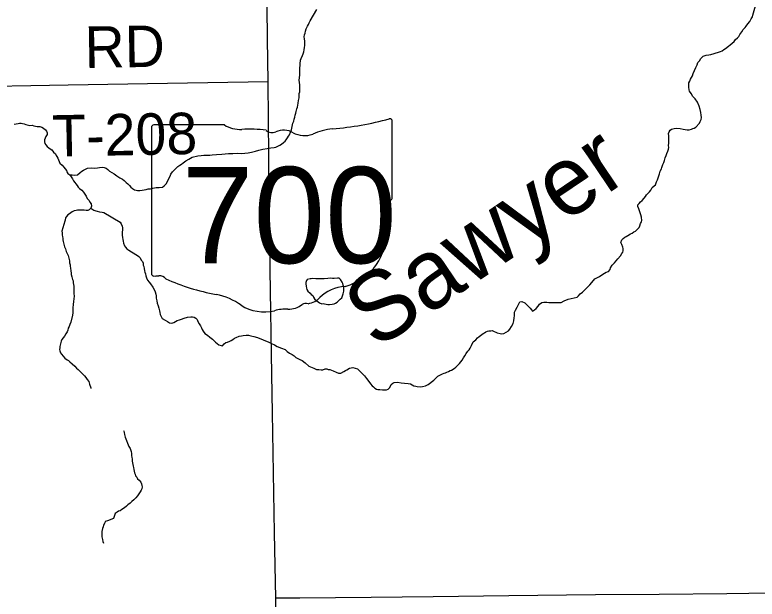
# Model space of a CAD drawing. Extents: x 0 to 34, y 0 to 22.
# Drawn here: x 6.59 to 7.606, y 15.407 to 16.207 of the extents above; entities that cross this region are included whole.
import ezdxf

# ---------------------------------------------------------------- set-up
doc = ezdxf.new("R2010")
doc.units = 0
for name, color, linetype in [('GM_X_Minor_Lake', 7, 'Continuous'), ('GM_X_Minor_River', 7, 'Continuous'), ('GM_X_Minor_River_Text', 7, 'Continuous'), ('GM_X_State_Route', 7, 'Continuous'), ('GM_X_State_Shield', 7, 'Continuous'), ('GM_X_Township_Road', 7, 'Continuous'), ('GM_X_Township_Road_Text', 7, 'Continuous')]:
    doc.layers.add(name, color=color, linetype=linetype)

msp = doc.modelspace()

# ---------------------------------------------------------------- linework, layer by layer
at = {"layer": 'GM_X_Minor_Lake'}
for points in [[(6.9939, 15.8453), (6.9898, 15.8445), (6.9894, 15.8433), (6.989, 15.8433), (6.988, 15.8406), (6.988, 15.8387), (6.9885, 15.8353), (6.9889, 15.8326), (6.9893, 15.8308), (6.9909, 15.8285), (6.994, 15.8259), (6.9956, 15.824), (6.9975, 15.8226), (6.9987, 15.8203), (6.9999, 15.8181), (7.003, 15.8155), (7.0069, 15.8125), (7.0099, 15.8114), (7.0118, 15.8115), (7.0138, 15.8111), (7.016, 15.8108), (7.0183, 15.8105), (7.0206, 15.8105), (7.024, 15.8106), (7.0271, 15.8114), (7.0289, 15.8122), (7.0311, 15.8136)], [(7.0311, 15.8136), (7.0316, 15.8138), (7.0334, 15.8158), (7.0349, 15.8177), (7.0372, 15.8197), (7.0382, 15.8223), (7.0393, 15.825), (7.04, 15.8285), (7.0399, 15.8308), (7.0399, 15.8338), (7.0394, 15.8368), (7.0386, 15.8391), (7.0378, 15.841), (7.0354, 15.8444), (7.0339, 15.8466), (7.0316, 15.8462), (7.0267, 15.8461), (7.0248, 15.846), (7.0221, 15.8463), (7.0183, 15.8459), (7.013, 15.8454), (7.008, 15.8456), (7.0019, 15.8455), (6.9977, 15.8458), (6.9955, 15.8454), (6.9939, 15.8453)]]:
    msp.add_lwpolyline(points, dxfattribs=at)
at = {"layer": 'GM_X_Minor_River'}
for points in [[(7.5969, 16.1999), (7.598, 16.2019), (7.5995, 16.2046), (7.6002, 16.2069), (7.6045, 16.2228)], [(6.9237, 16.0218), (6.9294, 16.0231), (6.9351, 16.024), (6.94, 16.0248), (6.9446, 16.0253), (6.9472, 16.0261), (6.9498, 16.0273), (6.9525, 16.0285), (6.9547, 16.0301), (6.9573, 16.0321), (6.9596, 16.034), (6.9611, 16.036), (6.9629, 16.0387), (6.9644, 16.041), (6.9658, 16.0429), (6.9669, 16.0464), (6.9684, 16.0495), (6.9704, 16.0586), (6.9715, 16.0613), (6.9722, 16.0644), (6.9729, 16.0671), (6.9736, 16.0697), (6.9743, 16.0724), (6.975, 16.0747), (6.9757, 16.0782), (6.9768, 16.0809), (6.9771, 16.0835), (6.9778, 16.0862), (6.9781, 16.09), (6.9788, 16.0935), (6.9791, 16.0965), (6.979, 16.0995), (6.9797, 16.1018), (6.9797, 16.1045), (6.98, 16.1076), (6.9799, 16.1114), (6.979, 16.1178), (6.98, 16.1247), (6.9798, 16.1323), (6.9804, 16.1399), (6.981, 16.1449), (6.9817, 16.1476), (6.9835, 16.1514), (6.9846, 16.1537), (6.9853, 16.1564), (6.986, 16.1591), (6.9863, 16.1625), (6.9866, 16.1652), (6.9866, 16.1682), (6.9865, 16.1713), (6.9861, 16.1743), (6.986, 16.177), (6.9863, 16.1796), (6.987, 16.1823), (6.9877, 16.185), (6.9884, 16.188), (6.9902, 16.1915), (6.9917, 16.1938), (6.9928, 16.1961), (6.9942, 16.1988), (7.0031, 16.2144)], [(7.4438, 15.9415), (7.4426, 15.9445), (7.4425, 15.9468), (7.4444, 15.9488), (7.4462, 15.9511), (7.4485, 15.953), (7.4511, 15.9558), (7.4533, 15.9585), (7.4544, 15.9604), (7.4585, 15.9647), (7.4603, 15.967), (7.4622, 15.9705), (7.4648, 15.9728), (7.4666, 15.9744), (7.4681, 15.9782), (7.4695, 15.9813), (7.471, 15.9851), (7.4724, 15.9894), (7.4734, 15.9932), (7.4749, 15.9963), (7.4756, 15.9982), (7.477, 16.002), (7.4781, 16.0047), (7.4792, 16.0078), (7.4802, 16.0112), (7.4813, 16.0143), (7.4824, 16.0174), (7.4835, 16.0204), (7.4845, 16.0231), (7.4849, 16.0254), (7.4848, 16.0281), (7.4851, 16.0315), (7.485, 16.0353), (7.485, 16.038), (7.4849, 16.0414), (7.4848, 16.0444), (7.4855, 16.0471), (7.487, 16.0494), (7.4889, 16.0506), (7.4923, 16.0514), (7.4949, 16.0519), (7.5006, 16.0516), (7.5045, 16.0506), (7.5102, 16.0496), (7.5129, 16.0496), (7.5159, 16.0505), (7.5178, 16.0513), (7.5196, 16.0521), (7.5219, 16.0533), (7.5271, 16.0587), (7.5282, 16.061), (7.5293, 16.0637), (7.5296, 16.0664), (7.5295, 16.0698), (7.5291, 16.0736), (7.5278, 16.0777), (7.5266, 16.0819), (7.5242, 16.0876), (7.521, 16.0921), (7.5179, 16.0954), (7.5155, 16.0995), (7.5135, 16.1025), (7.5127, 16.1044), (7.5123, 16.1082), (7.5126, 16.1113), (7.5125, 16.1139), (7.5136, 16.1162), (7.5147, 16.1189), (7.5162, 16.1212), (7.5173, 16.1235), (7.5183, 16.127), (7.5201, 16.1308), (7.5219, 16.1351), (7.5238, 16.1389), (7.5248, 16.142), (7.5271, 16.1443), (7.5289, 16.1474), (7.5319, 16.1505), (7.536, 16.1521), (7.5398, 16.1522), (7.5425, 16.153), (7.553, 16.1559), (7.5557, 16.1568), (7.5579, 16.158), (7.5602, 16.1595), (7.5628, 16.1611), (7.5666, 16.1642), (7.5692, 16.1662), (7.5718, 16.1682), (7.5744, 16.1705), (7.5762, 16.1736), (7.5792, 16.1756), (7.5811, 16.1775), (7.5825, 16.1802), (7.5848, 16.1837), (7.587, 16.1872), (7.5896, 16.1899), (7.591, 16.1918), (7.5932, 16.1949), (7.5958, 16.198), (7.5969, 16.1999)], [(6.5888, 16.0572), (6.5915, 16.0577), (6.5941, 16.0585), (6.596, 16.0589), (6.5983, 16.0586), (6.6002, 16.0582), (6.6025, 16.0579), (6.6048, 16.0568), (6.6082, 16.0561), (6.6102, 16.0558), (6.6132, 16.0559), (6.6159, 16.0552), (6.6182, 16.0545), (6.6201, 16.0541), (6.6239, 16.0542), (6.6266, 16.0531), (6.6289, 16.052), (6.6316, 16.0498), (6.6332, 16.0479)], [(6.6332, 16.0479), (6.634, 16.0457), (6.634, 16.0434), (6.6322, 16.0403), (6.6311, 16.038), (6.6304, 16.0361), (6.6305, 16.033), (6.6309, 16.0311), (6.6321, 16.0293), (6.634, 16.0267), (6.636, 16.0248), (6.6379, 16.0237), (6.6402, 16.0222), (6.6426, 16.0192), (6.6453, 16.0166), (6.6461, 16.0147), (6.6473, 16.0129), (6.6485, 16.011), (6.6493, 16.0084), (6.6513, 16.0042), (6.6544, 16.0012), (6.6567, 15.9986), (6.6587, 15.996), (6.6603, 15.9938), (6.6607, 15.9919), (6.6623, 15.9896), (6.665, 15.9882), (6.668, 15.9879), (6.6711, 15.9875), (6.6756, 15.988), (6.679, 15.9911), (6.6812, 15.9931), (6.6835, 15.9943), (6.6854, 15.9955), (6.6891, 15.9971), (6.6944, 15.9976), (6.6986, 15.9973), (6.7028, 15.9978), (6.7058, 15.9982), (6.7093, 15.9987), (6.7119, 15.998), (6.7146, 15.9969), (6.7169, 15.9954), (6.7193, 15.9932), (6.7224, 15.9914), (6.7258, 15.9895), (6.7293, 15.9866), (6.7336, 15.984), (6.737, 15.9822), (6.7394, 15.98), (6.7421, 15.9774), (6.7444, 15.9755), (6.7467, 15.9733), (6.7487, 15.971), (6.751, 15.9692), (6.7537, 15.9673), (6.7556, 15.967), (6.7575, 15.9667), (6.7606, 15.9667), (6.764, 15.9672), (6.7667, 15.9676), (6.7697, 15.9681), (6.7723, 15.9689), (6.7754, 15.969), (6.7788, 15.9698), (6.7833, 15.9707), (6.7875, 15.9708), (6.7917, 15.9709), (6.7943, 15.9728), (6.7973, 15.9763), (6.8006, 15.9829), (6.8024, 15.9863), (6.8031, 15.989), (6.8057, 15.9921), (6.8079, 15.9944), (6.8105, 15.9972), (6.8127, 15.9995), (6.8157, 16.0011), (6.818, 16.0027), (6.8202, 16.0046), (6.8236, 16.007), (6.8277, 16.0094), (6.8326, 16.0121), (6.8402, 16.0138), (6.8447, 16.0143), (6.8485, 16.0148), (6.8516, 16.0148), (6.8539, 16.0149), (6.8565, 16.015), (6.8599, 16.0154), (6.866, 16.0159), (6.8729, 16.0161), (6.882, 16.0171), (6.888, 16.0172), (6.8949, 16.0177), (6.9002, 16.0171), (6.9048, 16.0176), (6.909, 16.018), (6.9139, 16.0189), (6.9192, 16.0202), (6.9237, 16.0218)], [(6.665, 15.9882), (6.6685, 15.9825), (6.6701, 15.9799), (6.6752, 15.9732), (6.6764, 15.9713), (6.6783, 15.9691), (6.6814, 15.9668), (6.6838, 15.9642), (6.6857, 15.9616), (6.6873, 15.9586), (6.6889, 15.9556), (6.6913, 15.9526), (6.6925, 15.9507), (6.694, 15.9481), (6.6945, 15.9451), (6.6938, 15.9424), (6.6916, 15.9401), (6.6897, 15.9393), (6.6874, 15.9392), (6.6847, 15.9395), (6.6824, 15.9395), (6.6805, 15.9394), (6.6786, 15.9398), (6.6756, 15.9397), (6.6737, 15.9393), (6.671, 15.9388), (6.668, 15.9372), (6.6662, 15.9357), (6.6643, 15.9345), (6.6624, 15.9333), (6.6602, 15.931), (6.6591, 15.929), (6.6588, 15.926), (6.6583, 15.9244)], [(6.6938, 15.9424), (6.698, 15.9394), (6.7007, 15.9387), (6.7026, 15.938), (6.7057, 15.9373), (6.7091, 15.9367), (6.7115, 15.9362)], [(6.7115, 15.9362), (6.7338, 15.9231), (6.7354, 15.9209), (6.7366, 15.9175), (6.737, 15.9156), (6.7371, 15.9126), (6.7368, 15.9095), (6.7365, 15.9053), (6.7369, 15.9023), (6.7374, 15.8992), (6.7378, 15.897), (6.7383, 15.8943), (6.7399, 15.8909), (6.7411, 15.889), (6.743, 15.8868), (6.7457, 15.885), (6.7492, 15.8824), (6.7577, 15.8773), (6.7596, 15.8762), (6.7612, 15.8743), (6.7628, 15.8713), (6.7643, 15.8694), (6.7652, 15.8668), (6.7656, 15.8641), (6.7664, 15.8622), (6.7668, 15.8596), (6.7673, 15.8565), (6.7677, 15.8546), (6.7685, 15.8524), (6.769, 15.8497), (6.7698, 15.8471), (6.7714, 15.8437), (6.7734, 15.8411), (6.7753, 15.8385), (6.7785, 15.834), (6.7808, 15.8298), (6.782, 15.8276), (6.7825, 15.8245), (6.7833, 15.8223), (6.7834, 15.8192), (6.7842, 15.8154), (6.7847, 15.812), (6.7859, 15.8086), (6.7867, 15.8052), (6.7876, 15.8018), (6.788, 15.7992), (6.7888, 15.7965), (6.7896, 15.7946), (6.7916, 15.7913), (6.7955, 15.7891), (6.7986, 15.7872), (6.8016, 15.7854), (6.8047, 15.7847), (6.8073, 15.7859), (6.8096, 15.7871), (6.8118, 15.7883), (6.8149, 15.7895), (6.8179, 15.7903), (6.8217, 15.7916), (6.8262, 15.7928), (6.8308, 15.7933), (6.833, 15.7933), (6.835, 15.793), (6.8376, 15.7915), (6.8392, 15.7897), (6.8404, 15.787), (6.842, 15.7837), (6.844, 15.781), (6.8452, 15.7784), (6.846, 15.7761), (6.8476, 15.7739), (6.8499, 15.7705), (6.8534, 15.7683), (6.8565, 15.7657), (6.8604, 15.7628), (6.8643, 15.7587), (6.8689, 15.7553), (6.872, 15.7543), (6.8739, 15.7539), (6.8761, 15.7566), (6.8787, 15.7582), (6.881, 15.7587), (6.884, 15.7603), (6.8859, 15.7611), (6.8882, 15.7626), (6.8904, 15.7642), (6.8927, 15.765), (6.8968, 15.767), (6.8998, 15.7675), (6.9025, 15.7679)], [(7.2207, 15.7618), (7.223, 15.7645), (7.2256, 15.7665), (7.2274, 15.7677), (7.2308, 15.7704), (7.2327, 15.7716), (7.2346, 15.7728), (7.2368, 15.7736), (7.2387, 15.7744), (7.2414, 15.7744), (7.2433, 15.7745), (7.246, 15.7734), (7.2483, 15.7723), (7.2502, 15.7716), (7.254, 15.7705), (7.2559, 15.7702), (7.259, 15.7707), (7.2654, 15.7742), (7.2676, 15.7766), (7.2698, 15.78), (7.272, 15.7843), (7.273, 15.7881), (7.2733, 15.7919), (7.2736, 15.795), (7.274, 15.7973), (7.2739, 15.7999), (7.275, 15.8026), (7.2772, 15.8068), (7.2786, 15.8095), (7.2801, 15.8122), (7.2812, 15.8142), (7.2838, 15.8146), (7.2877, 15.8124), (7.29, 15.8102), (7.2927, 15.808), (7.2951, 15.8053), (7.297, 15.8031), (7.2982, 15.8012), (7.3012, 15.8032), (7.3035, 15.8048), (7.3064, 15.8079), (7.3079, 15.811), (7.3113, 15.8129), (7.3139, 15.8134), (7.3162, 15.8134), (7.3181, 15.8135), (7.3208, 15.8132), (7.3234, 15.8132), (7.3257, 15.8133), (7.3333, 15.8131), (7.3375, 15.8132), (7.342, 15.8155), (7.3473, 15.8176), (7.3556, 15.8197), (7.3594, 15.8205), (7.3613, 15.8221), (7.3635, 15.8248), (7.3669, 15.8271), (7.3695, 15.8302), (7.3725, 15.8326), (7.3747, 15.8349), (7.3769, 15.8373), (7.3795, 15.8404), (7.3836, 15.8454), (7.39, 15.8486), (7.3945, 15.8521), (7.3994, 15.8545), (7.4024, 15.8557), (7.4046, 15.8581), (7.4053, 15.8604), (7.4075, 15.8642), (7.4105, 15.8673), (7.4131, 15.87), (7.4153, 15.8728), (7.419, 15.877), (7.4208, 15.8801), (7.4219, 15.882), (7.4227, 15.884), (7.4226, 15.887), (7.4222, 15.8889), (7.4209, 15.8927), (7.4194, 15.8953), (7.4208, 15.8988), (7.4227, 15.9007), (7.4249, 15.9027), (7.4268, 15.9035), (7.429, 15.905), (7.4324, 15.907), (7.4347, 15.9082), (7.4373, 15.9098), (7.4395, 15.911), (7.4414, 15.9125), (7.4444, 15.916), (7.4455, 15.9183), (7.4465, 15.9214), (7.4476, 15.9237), (7.448, 15.9256), (7.4475, 15.9298), (7.4466, 15.9332), (7.4454, 15.9374), (7.4438, 15.9415)], [(6.6583, 15.9244), (6.6542, 15.9107), (6.6546, 15.9084), (6.6547, 15.9057), (6.6551, 15.9031), (6.6552, 15.9012), (6.6556, 15.8989), (6.656, 15.8966), (6.6569, 15.8928), (6.6577, 15.8894), (6.6589, 15.8864), (6.6601, 15.883), (6.6613, 15.8804), (6.6626, 15.8774), (6.6646, 15.8702), (6.6647, 15.8675), (6.6655, 15.8649), (6.6656, 15.8626), (6.666, 15.8607), (6.6665, 15.8562), (6.6669, 15.8539), (6.667, 15.8516), (6.6678, 15.8482), (6.6686, 15.8448), (6.6694, 15.8429), (6.6695, 15.8402), (6.6699, 15.8376), (6.6704, 15.8353), (6.6704, 15.833), (6.6705, 15.8296), (6.6706, 15.8254), (6.6707, 15.8216), (6.6704, 15.8182), (6.6701, 15.8144), (6.6694, 15.8102), (6.6691, 15.806), (6.6692, 15.8029), (6.6689, 15.7991), (6.6686, 15.7957), (6.6665, 15.7861), (6.6651, 15.7831), (6.664, 15.78), (6.6629, 15.7777), (6.6622, 15.7754), (6.6615, 15.7727), (6.6597, 15.77), (6.6575, 15.7669), (6.656, 15.7646), (6.6542, 15.7623), (6.6531, 15.7603), (6.652, 15.7565), (6.6517, 15.7546), (6.6513, 15.7527), (6.6514, 15.7508), (6.651, 15.7489), (6.6515, 15.747), (6.6523, 15.7443), (6.6535, 15.7421), (6.6558, 15.7395), (6.6582, 15.7369), (6.6613, 15.7347), (6.6632, 15.7336), (6.6651, 15.7317), (6.6682, 15.7291), (6.6717, 15.7258), (6.6741, 15.7231), (6.6764, 15.7213), (6.678, 15.7194), (6.6807, 15.7172), (6.6834, 15.7146), (6.685, 15.7124), (6.6869, 15.7101), (6.6889, 15.7075), (6.6909, 15.7049), (6.6913, 15.703), (6.6921, 15.7011), (6.6937, 15.6962), (6.6937, 15.6958), (6.6941, 15.6958)], [(6.9025, 15.7679), (6.9063, 15.7684), (6.9097, 15.7681), (6.9128, 15.7674), (6.917, 15.7663), (6.922, 15.7649), (6.9373, 15.7588), (6.9412, 15.757), (6.945, 15.7552), (6.9489, 15.7526), (6.955, 15.7504), (6.9596, 15.7486), (6.9627, 15.7461), (6.9658, 15.7438), (6.9693, 15.742), (6.972, 15.7402), (6.9743, 15.7379), (6.977, 15.7365), (6.9797, 15.735), (6.9832, 15.7336), (6.9871, 15.7306), (6.9921, 15.7258), (6.999, 15.7233), (7.0025, 15.7215), (7.0059, 15.7212), (7.009, 15.7208), (7.0112, 15.7209), (7.0146, 15.7221), (7.0169, 15.7222), (7.0188, 15.7215), (7.0208, 15.7211), (7.0231, 15.7204), (7.0257, 15.7193), (7.0296, 15.7175), (7.033, 15.7164), (7.0361, 15.7161), (7.0402, 15.7185), (7.0425, 15.7197), (7.0444, 15.7209), (7.0481, 15.7233), (7.0523, 15.7241), (7.0588, 15.7224), (7.0607, 15.7205), (7.0627, 15.7186), (7.0654, 15.7157), (7.0685, 15.7127), (7.0713, 15.7089), (7.0744, 15.7048), (7.0768, 15.7018), (7.0787, 15.6988), (7.0807, 15.6977), (7.0826, 15.6955), (7.0849, 15.6944), (7.0868, 15.6941), (7.0895, 15.6938), (7.0929, 15.6935), (7.0963, 15.6935), (7.0986, 15.6936), (7.1009, 15.6944), (7.1031, 15.6967), (7.1049, 15.7006), (7.1072, 15.7025), (7.1091, 15.7037), (7.1136, 15.7038), (7.1186, 15.7032), (7.1232, 15.7025), (7.1281, 15.7019), (7.1316, 15.7016), (7.1358, 15.699), (7.1385, 15.6983), (7.1404, 15.698), (7.1446, 15.6977), (7.148, 15.6981), (7.1518, 15.699), (7.1555, 15.7006), (7.1634, 15.7068), (7.1656, 15.7088), (7.169, 15.7123), (7.1724, 15.7139), (7.175, 15.7155), (7.1773, 15.7163), (7.1791, 15.7167), (7.181, 15.7175), (7.1833, 15.7187), (7.1855, 15.7199), (7.1874, 15.7203), (7.1912, 15.7227), (7.1934, 15.7243), (7.1964, 15.727), (7.1983, 15.7297), (7.2001, 15.7317), (7.202, 15.734), (7.2038, 15.7371), (7.2056, 15.7402), (7.2075, 15.7432), (7.2097, 15.7463), (7.2115, 15.7483), (7.213, 15.7506), (7.2148, 15.7541), (7.2174, 15.7591), (7.2207, 15.7618)], [(6.7384, 15.6378), (6.7388, 15.6367), (6.7392, 15.6352), (6.7397, 15.6322), (6.7409, 15.6284), (6.7458, 15.6159), (6.7477, 15.6129), (6.749, 15.6088), (6.7494, 15.6061), (6.7495, 15.6031), (6.7499, 15.6012), (6.7504, 15.5985), (6.7504, 15.5959), (6.7509, 15.5936), (6.7513, 15.5913), (6.7517, 15.5887), (6.7521, 15.5868), (6.7526, 15.5845), (6.753, 15.5819), (6.7535, 15.5796), (6.7543, 15.5777), (6.7551, 15.5758), (6.7566, 15.574), (6.7578, 15.5717), (6.7598, 15.5695), (6.7621, 15.5668), (6.7633, 15.5646), (6.7637, 15.5623), (6.7638, 15.5604), (6.7635, 15.5577), (6.7627, 15.5558), (6.7613, 15.5535), (6.7594, 15.5508), (6.7576, 15.5481), (6.7554, 15.5454), (6.7524, 15.5427), (6.7498, 15.5403), (6.7476, 15.538), (6.7446, 15.536), (6.7427, 15.5341), (6.7397, 15.5317), (6.7363, 15.5294), (6.7337, 15.5278), (6.7314, 15.527), (6.7296, 15.5258), (6.727, 15.5238), (6.7248, 15.5173), (6.7165, 15.5141), (6.7135, 15.5132), (6.7128, 15.5113), (6.7113, 15.5082), (6.7106, 15.5056), (6.7099, 15.5033), (6.7089, 15.4994), (6.7089, 15.496), (6.709, 15.4941), (6.709, 15.4922), (6.7099, 15.4884), (6.7103, 15.4858), (6.7111, 15.4835)]]:
    msp.add_lwpolyline(points, dxfattribs=at)
at = {"layer": 'GM_X_State_Route'}
msp.add_lwpolyline([(6.9601, 14.3385), (6.9588, 14.4363), (6.9583, 14.5087), (6.9569, 14.6447), (6.9545, 14.8525), (6.9526, 15.0617), (6.9494, 15.2806), (6.9469, 15.4082), (6.945, 15.4974), (6.9426, 15.6618), (6.9415, 15.7144), (6.9391, 15.8578), (6.9382, 15.9358), (6.9378, 15.962), (6.9363, 16.1152), (6.9355, 16.1742), (6.9333, 16.3902), (6.932, 16.532), (6.9312, 16.5929), (6.9284, 16.739), (6.9273, 16.8086), (6.9244, 16.9544), (6.9225, 17.0291)], dxfattribs=at)
at = {"layer": 'GM_X_State_Shield'}
for p, q in [((7.1065, 15.9567), (7.1065, 16.0614)), ((6.7769, 16.053), (6.7769, 15.8528)), ((6.8766, 16.0564), (6.7801, 16.0564)), ((7.1064, 15.9567), (7.1065, 15.9567))]:
    msp.add_line(p, q, dxfattribs=at)
for centre, major_axis, start_param, end_param in [((6.9891, 16.3292), (0.3495, 0), 4.814394, 5.042369), ((7.1028, 16.0618), (0.00367, 0), 6.141152, 7.989035), ((6.7806, 16.0534), (0.00382, 0), 1.712693, 3.28349), ((6.8996, 16.0796), (0.037, 0), 4.042523, 4.731795), ((6.9119, 15.9441), (0.133, 0), 1.404758, 1.657858), ((6.9421, 16.0544), (0.0107, 0), 3.836095, 5.185415), ((6.9578, 16.0313), (0.0222, 0), 0.950623, 2.079405), ((7.0336, 15.9953), (0.0703, 0), 1.699011, 2.107814), ((6.9864, 16.063), (0.0267, 0), 4.081561, 5.145723), ((7.1025, 15.9563), (0.00393, 0), 5.05454, 6.418171), ((7.1056, 15.949), (0.00568, 0), 1.883978, 3.671073), ((7.0695, 15.9358), (0.0341, 0), 5.934695, 6.695948), ((7.1196, 15.9129), (0.0248, 0), 2.387724, 3.262537), ((7.0086, 15.8995), (0.0874, 0), 5.101752, 6.440018), ((6.7807, 15.8524), (0.00385, 0), 3.00124, 4.508301), ((6.7813, 15.8729), (0.0294, 0), 4.665946, 4.897461), ((6.7873, 15.8413), (0.0106, 0), 0.519207, 1.627899), ((6.9211, 16.0211), (0.2524, 0), 4.195997, 4.488961), ((7.0455, 15.7967), (0.0479, 0), 1.647645, 2.488434), ((6.8459, 15.7629), (0.079, 0), 0.823519, 1.323587), ((6.9848, 15.8334), (0.0282, 0), 4.937069, 5.64225), ((6.9313, 15.8403), (0.0501, 0), 4.026481, 4.996735), ((6.9602, 15.7711), (0.0412, 0), 1.495662, 1.94098), ((6.9639, 15.8253), (0.0267, 0), 4.691044, 5.507374), ((6.988, 15.8059), (0.00752, 0), 1.147584, 2.315152)]:
    msp.add_ellipse(centre, major_axis=major_axis, ratio=0.8, start_param=start_param, end_param=end_param, dxfattribs=at)
at = {"layer": 'GM_X_Township_Road'}
for points in [[(6.9363, 16.1152), (6.7989, 16.1131), (6.6629, 16.111), (6.5086, 16.1083), (6.4334, 16.107), (6.4312, 16.1066)], [(8.7581, 15.4244), (8.6955, 15.4237), (8.4209, 15.4213), (8.145, 15.4195), (7.8874, 15.4172), (7.7627, 15.416), (7.7494, 15.4167), (7.6543, 15.4153), (7.5646, 15.4139), (7.4718, 15.4132), (7.3848, 15.4126), (7.2659, 15.4111), (7.1624, 15.41), (7.0775, 15.409), (6.98, 15.4082), (6.9469, 15.4082)]]:
    msp.add_lwpolyline(points, dxfattribs=at)

# ---------------------------------------------------------------- texts
at = {"layer": 'GM_X_Minor_River_Text'}
msp.add_text('Sawyer', height=0.09476, rotation=34.0166, dxfattribs=at).set_placement((7.0838, 15.7474))
at = {"layer": 'GM_X_State_Shield'}
msp.add_text('700', height=0.13184, dxfattribs=at).set_placement((6.8184, 15.8669))
at = {"layer": 'GM_X_Township_Road_Text'}
for s, rotation, p in [('RD', 0.9872, (6.6857, 16.1343)), ('T-208', 1.1178, (6.6414, 16.0128))]:
    msp.add_text(s, height=0.05682, rotation=rotation, dxfattribs=at).set_placement(p)

doc.saveas('drawing.dxf')
